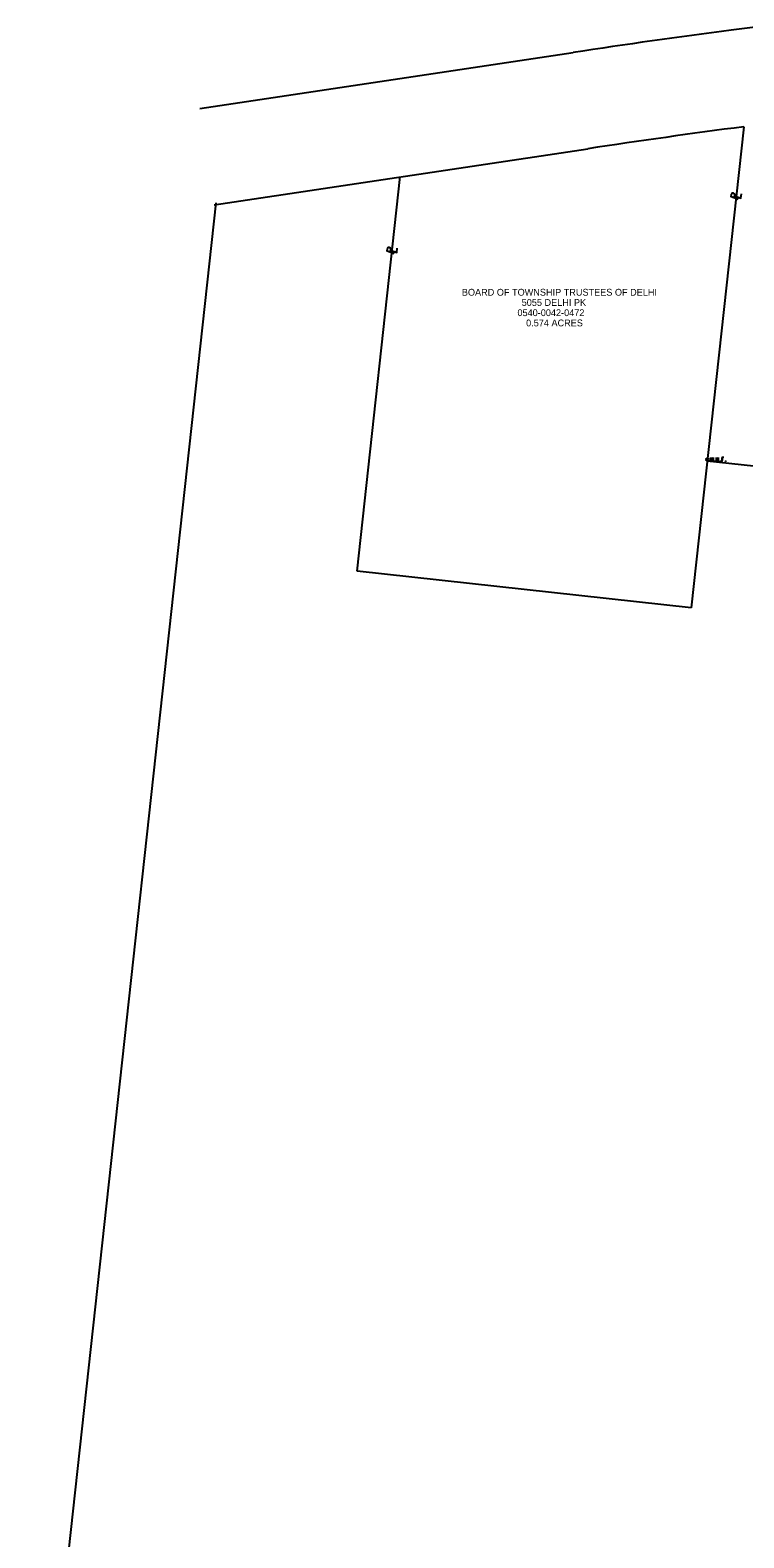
# Model space of a CAD drawing. Extents: x 1369159 to 1370720, y 404461 to 406422.
# Drawn here: x 1369178 to 1369471, y 405265 to 405884 of the extents above; entities that cross this region are included whole.
import ezdxf

# ---------------------------------------------------------------- set-up
doc = ezdxf.new("R2010")
doc.units = 0
for name, color, linetype in [('_CIVIL_CONSTRUCTION', 7, 'Continuous'), ('Default', 7, 'Continuous'), ('DR_P_Storm_Sewer', 7, 'Continuous'), ('GK_Drainage_Nodes', 7, 'Continuous'), ('XS_X_Pavt', 7, 'Continuous'), ('XS_X_Subgrade', 7, 'Continuous')]:
    doc.layers.add(name, color=color, linetype=linetype)

msp = doc.modelspace()

# ---------------------------------------------------------------- linework, layer by layer
at = {"layer": '_CIVIL_CONSTRUCTION'}
for p, q in [((1369457.19, 405706.56), (1369457.19, 405708.16)), ((1369457.19, 405708.16), (1369457.69, 405706.56)), ((1369457.69, 405706.56), (1369458.18, 405708.16)), ((1369458.18, 405708.16), (1369458.18, 405706.56)), ((1369458.88, 405706.7), (1369458.92, 405706.75)), ((1369458.88, 405706.64), (1369458.88, 405706.7)), ((1369458.92, 405706.59), (1369458.88, 405706.64)), ((1369458.92, 405706.75), (1369458.95, 405706.78)), ((1369458.95, 405706.56), (1369458.92, 405706.59)), ((1369458.95, 405706.78), (1369459.01, 405706.78)), ((1369459.01, 405706.56), (1369458.95, 405706.56)), ((1369459.01, 405706.78), (1369459.04, 405706.75)), ((1369459.04, 405706.59), (1369459.01, 405706.56)), ((1369459.04, 405706.75), (1369459.07, 405706.7)), ((1369459.07, 405706.64), (1369459.04, 405706.59)), ((1369459.07, 405706.7), (1369459.07, 405706.64)), ((1369459.56, 405706.56), (1369459.56, 405708.16)), ((1369459.56, 405708.16), (1369460.38, 405706.56)), ((1369460.38, 405706.56), (1369460.38, 405708.16)), ((1369461.1, 405706.7), (1369461.13, 405706.75)), ((1369461.1, 405706.64), (1369461.1, 405706.7)), ((1369461.13, 405706.59), (1369461.1, 405706.64)), ((1369461.13, 405706.75), (1369461.17, 405706.78)), ((1369461.17, 405706.56), (1369461.13, 405706.59)), ((1369461.17, 405706.78), (1369461.22, 405706.78)), ((1369461.22, 405706.56), (1369461.17, 405706.56)), ((1369461.22, 405706.78), (1369461.25, 405706.75)), ((1369461.25, 405706.59), (1369461.22, 405706.56)), ((1369461.25, 405706.75), (1369461.29, 405706.7)), ((1369461.29, 405706.64), (1369461.25, 405706.59)), ((1369461.29, 405706.7), (1369461.29, 405706.64)), ((1369462.53, 405708.16), (1369461.77, 405708.16)), ((1369461.77, 405708.16), (1369461.77, 405706.56)), ((1369461.77, 405707.38), (1369462.31, 405707.38)), ((1369463.25, 405706.7), (1369463.28, 405706.75)), ((1369463.25, 405706.64), (1369463.25, 405706.7)), ((1369463.28, 405706.59), (1369463.25, 405706.64)), ((1369463.28, 405706.75), (1369463.32, 405706.78)), ((1369463.32, 405706.56), (1369463.28, 405706.59)), ((1369463.32, 405706.78), (1369463.37, 405706.78)), ((1369463.37, 405706.56), (1369463.32, 405706.56)), ((1369463.37, 405706.78), (1369463.4, 405706.75)), ((1369463.4, 405706.59), (1369463.37, 405706.56)), ((1369463.4, 405706.75), (1369463.44, 405706.7)), ((1369463.44, 405706.64), (1369463.4, 405706.59)), ((1369463.44, 405706.7), (1369463.44, 405706.64))]:
    msp.add_line(p, q, dxfattribs=at)
msp.add_circle((1369455.75, 405707.37), 0.497, dxfattribs=at)
at = {"layer": 'Default'}
msp.add_line((1369177.85, 405114.02), (1369254.15, 405812.77), dxfattribs=at)
at = {"layer": 'DR_P_Storm_Sewer'}
for p, q in [((1369470.76, 405844.03), (1369449.19, 405646.52)), ((1369312.01, 405661.5), (1369329.7, 405823.53)), ((1369466.93, 405814.75), (1369467.08, 405816.04)), ((1369467.64, 405815.48), (1369467.64, 405815.48)), ((1369325.68, 405792.43), (1369325.82, 405793.72)), ((1369326.38, 405793.16), (1369326.38, 405793.16)), ((1369660.06, 405685), (1369455.76, 405706.68)), ((1369449.19, 405646.52), (1369312.01, 405661.5))]:
    msp.add_line(p, q, dxfattribs=at)
for points in [[(1369468.47, 405814.16), (1369465.61, 405815.26), (1369465.72, 405816.29)], [(1369466.72, 405815.85), (1369469.57, 405814.74), (1369469.76, 405816.48)], [(1369327.21, 405791.84), (1369324.35, 405792.94), (1369324.46, 405793.97)], [(1369325.46, 405793.53), (1369328.31, 405792.42), (1369328.5, 405794.16)]]:
    msp.add_lwpolyline(points, dxfattribs=at)
for centre in [(1369466.39, 405816.11), (1369325.13, 405793.79)]:
    msp.add_arc(centre, 0.69, 354.23899, 165.0961, dxfattribs=at)
at = {"layer": 'XS_X_Pavt'}
msp.add_line((1369247.5, 405851.56), (1369400.7, 405874.52), dxfattribs=at)
for centre, radius, start, end in [((1369834.84, 403043.1), 2864.49, 93.16294, 97.40586), ((1369852.34, 402914.17), 2994.6, 97.41997, 98.67441)]:
    msp.add_arc(centre, radius, start, end, dxfattribs=at)
at = {"layer": 'XS_X_Subgrade'}
msp.add_line((1369253.43, 405812), (1369406.68, 405834.97), dxfattribs=at)
msp.add_arc((1369852.21, 402915.08), 2953.69, 97.42016, 98.67562, dxfattribs=at)

# ---------------------------------------------------------------- texts
at = {"layer": 'GK_Drainage_Nodes'}
for s, p in [('BOARD OF TOWNSHIP TRUSTEES OF DELHI', (1369355.02, 405774.66)), ('5055 DELHI PK', (1369379.58, 405770.46)), ('0540-0042-0472', (1369377.84, 405766.26)), ('0.574 ACRES', (1369381.4, 405762.06))]:
    msp.add_text(s, height=2.8, dxfattribs=at).set_placement(p)

doc.saveas('drawing.dxf')
